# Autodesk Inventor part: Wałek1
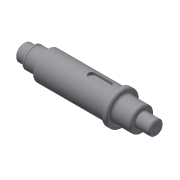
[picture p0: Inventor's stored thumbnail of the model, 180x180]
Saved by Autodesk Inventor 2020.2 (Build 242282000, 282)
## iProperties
Created: 2005-01
Part Number: Wałek1
Document SubType Name: Modeling
Designer: F.Stasiak
Manufacturer: Standard
Standards Organization: Custom
Density: 1 g/cm^3
Material: Ogólny
Appearance: Domyślna
Manager: www.cadconsulting.pl
Company: Fabian Stasiak CAD Consulting
Author: F.Stasiak
Subject: Zbiór ćwiczeń. Autodesk Inventor 2020. Kurs podstawowy
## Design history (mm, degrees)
sketch "Szkic1"
  geometry: L1 (0, 0)-(0, 17.5); L2 (0, 17.5)-(20, 17.5); L3 (20, 17.5)-(20, 22.5); L4 (20, 22.5)-(50, 22.5); L5 (50, 22.5)-(50, 30); L6 (50, 30)-(200, 30); L7 (200, 30)-(200, 35); L8 (200, 35)-(210, 35); L9 (210, 35)-(210, 25); L10 (210, 25)-(250, 25); L11 (250, 25)-(250, 15); L12 (250, 15)-(280, 15); L13 (280, 15)-(280, 0); L14 (0, 0)-(280, 0); 1 further point
  constraints: 28 end point, 11 parallel, 2 perpendicular, 1 coincident, 1 vertical
  dimensions: "d31" = 10 distance of L7.end L8.end; "d32" = 150 distance of L5.end L6.end; "d33" = 180 distance between parallel lines of L3 L7; "d34" = 200 distance between parallel lines of L1 L7; "d35" = 50 distance between parallel lines of L11 L7; "d38" = 30 diameter of L12 L14; "d39" = 50 diameter of L10 L14; "d40" = 70 diameter of L8 L14; "d41" = 60 diameter of L6 L14; "d42" = 45 diameter of L4 L14; "d43" = 35 diameter of L2 L14; "d60" = 280 distance between parallel lines of L13 L1
revolve "Obrót3" sketch "Szkic1" stored, may be unused: angle "d45" = 90 deg
sketch "Szkic2"
  geometry: L1 (23.9, 22.5)-(26.5, 22.5); L2 (26.5, 22.5)-(26.5, 21.25); L3 (26.5, 21.25)-(23.9, 21.25); L4 (23.9, 21.25)-(23.9, 22.5); L5 (20, 22.5)-(50, 22.5) reference; L6 (17, 0)-(59, 0) reference
  constraints: 8 end point, 2 parallel, 1 collinear, 1 horizontal, 1 perpendicular
  dimensions: "d46" = 2.6 distance of L1.start L1.end; "d47" = 42.5 diameter of L3.end L6; "d48" = 6.5 distance from line of L5.start L2
revolve "Obrót4" sketch "Szkic2" stored, may be unused: angle "d49" = 90 deg
sketch "Szkic3"
  geometry: L1 (26.5, 22.5)-(50, 22.5) reference; L2 (50, -30)-(50, 30) reference; L3 (24.159, 0)-(57.627, 0) reference; L4 (46, 22.5)-(47.12, 22.2); L5 (47.12, 22.2)-(49.706, 22.2); L6 (50.3, 22.884)-(50, 25.018); L7 (46, 22.5)-(50, 25.018); A1 r 0.6 centre (49.706, 22.8) between (49.706, 22.2) and (50.3, 22.884)
  constraints: 8 end point, 2 point on circle, 2 point on line, 2 tangent, 1 centre point, 1 perpendicular
  dimensions: "d50" = 0.6 radius of A1; "d51" = 0.3 distance between parallel lines of L1 L5; "d52" = 0.3 distance from line of L6.start L2; "d53" = 4 distance from line of L2 L4.start; "d54" = 15 deg angle of L1 L4; "d55" = 8 deg angle of L2 L6
revolve "Obrót5" sketch "Szkic3" stored, may be unused: angle "d56" = 90 deg
chamfer "Faza1" distance "d57" = 2; stored, may be unused: second distance "d58" = 2, angle "d59" = 45 deg
fillet "Zaokrąglenie1" dims "d61" = 5
fillet "Zaokrąglenie2" dims "d62" = 2
node "Płaszczyzna konstrukcyjna1"
sketch "Szkic4"
  geometry: L1 (-153, 0)-(239, 0) reference; L2 (20, 8)-(52, 8); L3 (52, -8)-(20, -8); L4 (75, -35)-(75, 35) reference; A1 r 8 centre (52, 0) between (52, -8) and (52, 8); A2 r 8 centre (20, 0) between (20, 8) and (20, -8)
  constraints: 4 end point, 4 point on circle, 4 tangent, 2 centre point, 2 parallel, 1 point on line
  dimensions: "d63" = 8 radius of A1; "d64" = 48 dimension on A1 A2; "d65" = 15 distance edge to line of A1 L4
extrude "Wyciągnięcie proste1" cut sketch "Szkic4" distance "d66" = 6; taper "d67" = 0 deg
node "Bryła1"
node "Korpusy bryłowe"
node "Korpusy powierzchniowe"
